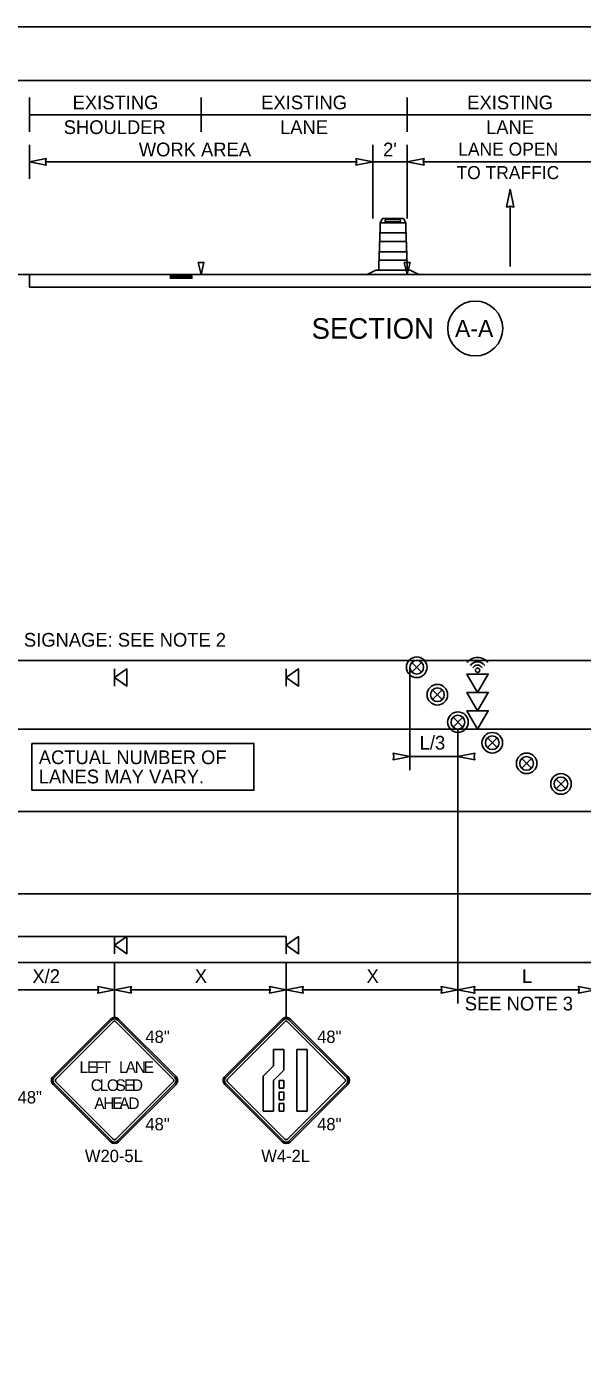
# Model space of a CAD drawing. Extents: x 99999 to 100116, y 99995 to 100013.
# Drawn here: x 100004.26 to 100007.5, y 100002.86 to 100010.69 of the extents above; entities that cross this region are included whole.
import ezdxf

# ---------------------------------------------------------------- set-up
doc = ezdxf.new("R2010")
doc.units = 0
for name, color, linetype in [('RD_ED_ShoulderPavedEdge', 7, 'Continuous'), ('RD_MK_LineEdgeWhite', 7, 'Continuous'), ('RD_MK_LineEdgeYellow', 7, 'Continuous'), ('RD_MK_LineLane', 7, 'Continuous'), ('SH_GI_PlotLimits', 7, 'Continuous'), ('SH_GI_SheetBorder', 7, 'Continuous'), ('SH_TI_Tables', 7, 'Continuous'), ('SH_TI_WZSectionCut', 7, 'Continuous'), ('TR_SN_ConstructionSigns', 7, 'Continuous'), ('TR_WZ_ArrowLeftStrRightTurn', 7, 'Continuous'), ('TR_WZ_PortableSignMountBlk-Org', 7, 'Continuous'), ('TR_WZ_SequentialArrowSign', 7, 'Continuous'), ('TR_WZ_TrafficSafetyDrum', 7, 'Continuous'), ('TR_WZ_TrafficSafetyDrumElev', 7, 'Continuous'), ('TR_WZ_WorkZoneDetails', 7, 'Continuous'), ('TR_WZ_WorkZoneTextCurrent', 7, 'Continuous')]:
    doc.layers.add(name, color=color, linetype=linetype)

msp = doc.modelspace()

# ---------------------------------------------------------------- linework, layer by layer
at = {"layer": 'RD_ED_ShoulderPavedEdge'}
for p, q in [((100000.8283, 100006.9957), (100015.62, 100006.9957)), ((100000.8283, 100005.2357), (100015.62, 100005.2357))]:
    msp.add_line(p, q, dxfattribs=at)
at = {"layer": 'RD_MK_LineEdgeWhite'}
msp.add_line((100000.8283, 100005.6357), (100015.62, 100005.6357), dxfattribs=at)
at = {"layer": 'RD_MK_LineEdgeYellow'}
msp.add_line((100000.8283, 100006.5957), (100015.62, 100006.5957), dxfattribs=at)
at = {"layer": 'RD_MK_LineLane'}
msp.add_lwpolyline([(100015.62, 100006.1157), (100000.8283, 100006.1157)], dxfattribs=at)
at = {"layer": 'SH_GI_PlotLimits'}
msp.add_lwpolyline([(99999.0625, 99999.6875), (100016.0625, 99999.6875), (100016.0625, 100010.6875), (99999.0625, 100010.6875)], close=True, dxfattribs=at)
at = {"layer": 'SH_GI_SheetBorder'}
msp.add_line((100000, 100010.375), (100015.75, 100010.375), dxfattribs=at)
at = {"layer": 'SH_TI_Tables'}
msp.add_lwpolyline([(100004.2941, 100006.511), (100005.5872, 100006.511), (100005.5872, 100006.239), (100004.2941, 100006.239)], close=True, dxfattribs=at)
at = {"layer": 'SH_TI_WZSectionCut'}
for p, q in [((100004.2794, 100010.075), (100004.2794, 100010.275)), ((100005.2794, 100010.075), (100005.2794, 100010.275)), ((100006.4794, 100010.075), (100006.4794, 100010.275)), ((100004.2794, 100010.175), (100005.2794, 100010.175)), ((100005.2794, 100010.175), (100006.4794, 100010.175)), ((100006.4794, 100010.175), (100007.6794, 100010.175)), ((100004.2794, 100009.801), (100004.2794, 100010.001)), ((100006.2794, 100009.57), (100006.2794, 100010.001)), ((100006.4794, 100009.57), (100006.4794, 100010.001)), ((100006.1857, 100009.901), (100004.3731, 100009.901)), ((100006.4794, 100009.901), (100006.2794, 100009.901)), ((100007.5857, 100009.901), (100006.5731, 100009.901)), ((100004.2794, 100009.2449), (100004.2794, 100009.1699)), ((100008.6794, 100009.2449), (100004.2794, 100009.2449)), ((100005.0964, 100009.2397), (100005.2294, 100009.2397)), ((100005.0964, 100009.2341), (100005.2294, 100009.2341)), ((100005.0964, 100009.2284), (100005.2294, 100009.2284)), ((100008.6794, 100009.1699), (100004.2794, 100009.1699)), ((100005.0964, 100009.2232), (100005.2294, 100009.2232))]:
    msp.add_line(p, q, dxfattribs=at)
for points in [[(100004.2794, 100009.901), (100004.3777, 100009.8817), (100004.3731, 100009.901), (100004.3777, 100009.9203)], [(100006.2794, 100009.901), (100006.1811, 100009.8817), (100006.1857, 100009.901), (100006.1811, 100009.9203)], [(100006.4794, 100009.901), (100006.5777, 100009.8817), (100006.5731, 100009.901), (100006.5777, 100009.9203)], [(100005.2627, 100009.3147), (100005.296, 100009.3147), (100005.2794, 100009.2449)], [(100006.4627, 100009.3147), (100006.4961, 100009.3147), (100006.4794, 100009.2449)]]:
    msp.add_lwpolyline(points, close=True, dxfattribs=at)
msp.add_circle((100006.8759, 100008.93), 0.16, dxfattribs=at)
msp.add_open_spline([(100004.2794, 100009.2449), (100004.0282, 100009.2449), (100003.9027, 100009.1828), (100003.7773, 100009.1828)], degree=2, dxfattribs=at)
at = {"layer": 'TR_SN_ConstructionSigns'}
for p, q in [((100004.7514, 100004.9058), (100004.4173, 100004.5717)), ((100004.7574, 100004.8999), (100004.4233, 100004.5658)), ((100004.4332, 100004.5558), (100004.7673, 100004.8899)), ((100004.7832, 100004.8899), (100005.1173, 100004.5558)), ((100005.1273, 100004.5658), (100004.7932, 100004.8999)), ((100005.1333, 100004.5717), (100004.7991, 100004.9058)), ((100005.7514, 100004.9058), (100005.4173, 100004.5717)), ((100005.7574, 100004.8999), (100005.4233, 100004.5658)), ((100005.4332, 100004.5558), (100005.7673, 100004.8899)), ((100005.7832, 100004.8899), (100006.1173, 100004.5558)), ((100006.1273, 100004.5658), (100005.7932, 100004.8999)), ((100006.1333, 100004.5717), (100005.7991, 100004.9058)), ((100005.7612, 100004.7279), (100005.7007, 100004.7279)), ((100005.7007, 100004.7279), (100005.7007, 100004.6334)), ((100005.7007, 100004.6334), (100005.7007, 100004.7279)), ((100005.7007, 100004.7279), (100005.7612, 100004.7279)), ((100005.7612, 100004.6083), (100005.7612, 100004.7279)), ((100005.7612, 100004.7279), (100005.7612, 100004.6083)), ((100005.8969, 100004.7279), (100005.8365, 100004.7279)), ((100005.8365, 100004.7279), (100005.8365, 100004.3679)), ((100005.8365, 100004.3679), (100005.8365, 100004.7279)), ((100005.8365, 100004.7279), (100005.8969, 100004.7279)), ((100005.8969, 100004.3679), (100005.8969, 100004.7279)), ((100005.8969, 100004.7279), (100005.8969, 100004.3679)), ((100005.7007, 100004.6334), (100005.6403, 100004.5729)), ((100005.6403, 100004.5729), (100005.7007, 100004.6334)), ((100004.7673, 100004.2058), (100004.4332, 100004.5399)), ((100005.1173, 100004.5399), (100004.7832, 100004.2058)), ((100005.7673, 100004.2058), (100005.4332, 100004.5399)), ((100005.6403, 100004.5729), (100005.6403, 100004.3679)), ((100005.6403, 100004.3679), (100005.6403, 100004.5729)), ((100005.7007, 100004.5479), (100005.7612, 100004.6083)), ((100005.7612, 100004.6083), (100005.7007, 100004.5479)), ((100005.7007, 100004.3679), (100005.7007, 100004.5479)), ((100005.7007, 100004.5479), (100005.7007, 100004.3679)), ((100005.7612, 100004.5479), (100005.7345, 100004.5479)), ((100005.7345, 100004.5479), (100005.7345, 100004.5029)), ((100005.7345, 100004.5029), (100005.7345, 100004.5479)), ((100005.7345, 100004.5479), (100005.7612, 100004.5479)), ((100005.7612, 100004.5029), (100005.7612, 100004.5479)), ((100005.7612, 100004.5479), (100005.7612, 100004.5029)), ((100006.1173, 100004.5399), (100005.7832, 100004.2058)), ((100004.4173, 100004.524), (100004.7514, 100004.1899)), ((100004.4233, 100004.53), (100004.7574, 100004.1959)), ((100004.7932, 100004.1959), (100005.1273, 100004.53)), ((100004.7991, 100004.1899), (100005.1333, 100004.524)), ((100005.4173, 100004.524), (100005.7514, 100004.1899)), ((100005.4233, 100004.53), (100005.7574, 100004.1959)), ((100005.7345, 100004.5029), (100005.7612, 100004.5029)), ((100005.7612, 100004.5029), (100005.7345, 100004.5029)), ((100005.7612, 100004.4804), (100005.7345, 100004.4804)), ((100005.7345, 100004.4804), (100005.7345, 100004.4354)), ((100005.7345, 100004.4354), (100005.7345, 100004.4804)), ((100005.7345, 100004.4804), (100005.7612, 100004.4804)), ((100005.7612, 100004.4354), (100005.7612, 100004.4804)), ((100005.7612, 100004.4804), (100005.7612, 100004.4354)), ((100005.7932, 100004.1959), (100006.1273, 100004.53)), ((100005.7991, 100004.1899), (100006.1333, 100004.524)), ((100005.7345, 100004.4354), (100005.7612, 100004.4354)), ((100005.7612, 100004.4354), (100005.7345, 100004.4354)), ((100005.7612, 100004.4129), (100005.7345, 100004.4129)), ((100005.7345, 100004.4129), (100005.7345, 100004.3679)), ((100005.7345, 100004.3679), (100005.7345, 100004.4129)), ((100005.7345, 100004.4129), (100005.7612, 100004.4129)), ((100005.7612, 100004.3679), (100005.7612, 100004.4129)), ((100005.7612, 100004.4129), (100005.7612, 100004.3679)), ((100005.6403, 100004.3679), (100005.7007, 100004.3679)), ((100005.7007, 100004.3679), (100005.6403, 100004.3679)), ((100005.7345, 100004.3679), (100005.7612, 100004.3679)), ((100005.7612, 100004.3679), (100005.7345, 100004.3679)), ((100005.8365, 100004.3679), (100005.8969, 100004.3679)), ((100005.8969, 100004.3679), (100005.8365, 100004.3679))]:
    msp.add_line(p, q, dxfattribs=at)
for centre, radius, start, end in [((100004.7753, 100004.882), 0.0338, 45, 135), ((100004.7753, 100004.882), 0.0253, 45, 135), ((100004.7753, 100004.882), 0.0113, 45, 135), ((100005.7753, 100004.882), 0.0338, 45, 135), ((100005.7753, 100004.882), 0.0253, 45, 135), ((100005.7753, 100004.882), 0.0113, 45, 135), ((100004.4412, 100004.5479), 0.0338, 135, 225.00001), ((100004.4412, 100004.5479), 0.0253, 135, 225.00001), ((100004.4412, 100004.5479), 0.0113, 135, 225.00001), ((100005.1094, 100004.5479), 0.0113, 315.00002, 45), ((100005.1094, 100004.5479), 0.0253, 315.00002, 45), ((100005.1094, 100004.5479), 0.0338, 315.00001, 45.00001), ((100005.4412, 100004.5479), 0.0338, 135, 225.00001), ((100005.4412, 100004.5479), 0.0253, 135, 225.00001), ((100005.4412, 100004.5479), 0.0113, 135, 225.00001), ((100006.1094, 100004.5479), 0.0113, 315.00002, 45), ((100006.1094, 100004.5479), 0.0253, 315.00002, 45), ((100006.1094, 100004.5479), 0.0338, 315.00001, 45.00001), ((100004.7753, 100004.2138), 0.0338, 225.00001, 315.00001), ((100004.7753, 100004.2138), 0.0253, 225.00001, 315.00002), ((100004.7753, 100004.2138), 0.0113, 225.00001, 315.00002), ((100005.7753, 100004.2138), 0.0338, 225.00001, 315.00001), ((100005.7753, 100004.2138), 0.0253, 225.00001, 315.00002), ((100005.7753, 100004.2138), 0.0113, 225.00001, 315.00002)]:
    msp.add_arc(centre, radius, start, end, dxfattribs=at)
at = {"layer": 'TR_WZ_ArrowLeftStrRightTurn'}
msp.add_line((100007.0794, 100009.6418), (100007.0794, 100009.292), dxfattribs=at)
msp.add_lwpolyline([(100007.0794, 100009.742), (100007.1, 100009.6369), (100007.0794, 100009.6418), (100007.0588, 100009.6369)], close=True, dxfattribs=at)
at = {"layer": 'TR_WZ_PortableSignMountBlk-Org'}
for p, q in [((100004.7753, 100006.8458), (100004.7753, 100006.9458)), ((100005.7753, 100006.8458), (100005.7753, 100006.9458)), ((100004.7753, 100005.2858), (100004.7753, 100005.3858)), ((100005.7753, 100005.2858), (100005.7753, 100005.3858))]:
    msp.add_line(p, q, dxfattribs=at)
for points in [[(100004.7753, 100006.8957), (100004.8471, 100006.9458), (100004.8471, 100006.8458)], [(100005.7753, 100006.8957), (100005.8471, 100006.9458), (100005.8471, 100006.8458)], [(100004.7753, 100005.3357), (100004.8471, 100005.3858), (100004.8471, 100005.2858)], [(100005.7753, 100005.3357), (100005.8471, 100005.3858), (100005.8471, 100005.2858)]]:
    msp.add_lwpolyline(points, close=True, dxfattribs=at)
at = {"layer": 'TR_WZ_SequentialArrowSign'}
for points in [[(100006.8895, 100006.8091), (100006.8278, 100006.9157), (100006.9513, 100006.9157), (100006.8895, 100006.8091)], [(100006.9513, 100006.9157), (100006.8278, 100006.9157), (100006.8895, 100006.8091), (100006.9513, 100006.9157)], [(100006.8895, 100006.7024), (100006.8278, 100006.8091), (100006.8895, 100006.8091), (100006.9513, 100006.8091), (100006.8895, 100006.7024)], [(100006.9513, 100006.8091), (100006.8895, 100006.8091), (100006.8278, 100006.8091), (100006.8895, 100006.7024), (100006.9513, 100006.8091)], [(100006.8895, 100006.5957), (100006.8278, 100006.7024), (100006.8895, 100006.7024), (100006.9513, 100006.7024), (100006.8895, 100006.5957)], [(100006.9513, 100006.7024), (100006.8895, 100006.7024), (100006.8278, 100006.7024), (100006.8895, 100006.5957), (100006.9513, 100006.7024)]]:
    msp.add_lwpolyline(points, dxfattribs=at)
msp.add_circle((100006.8895, 100006.9382), 0.0125, dxfattribs=at)
for radius, start, end in [(0.075, 37.32912, 142.67088), (0.05, 33.97816, 146.02184), (0.03, 27.15796, 152.84204)]:
    msp.add_arc((100006.8895, 100006.9382), radius, start, end, dxfattribs=at)
at = {"layer": 'TR_WZ_TrafficSafetyDrum'}
for p, q in [((100006.507, 100006.9274), (100006.5636, 100006.984)), ((100006.5636, 100006.9274), (100006.507, 100006.984)), ((100006.627, 100006.7674), (100006.6836, 100006.824)), ((100006.6836, 100006.7674), (100006.627, 100006.824)), ((100006.747, 100006.6074), (100006.8036, 100006.664)), ((100006.8036, 100006.6074), (100006.747, 100006.664)), ((100006.947, 100006.4874), (100007.0036, 100006.544)), ((100007.0036, 100006.4874), (100006.947, 100006.544)), ((100007.147, 100006.3674), (100007.2036, 100006.424)), ((100007.2036, 100006.3674), (100007.147, 100006.424)), ((100007.347, 100006.2474), (100007.4036, 100006.304)), ((100007.4036, 100006.2474), (100007.347, 100006.304))]:
    msp.add_line(p, q, dxfattribs=at)
for centre, radius in [((100006.5353, 100006.9557), 0.06), ((100006.5353, 100006.9557), 0.06), ((100006.5353, 100006.9557), 0.04), ((100006.6553, 100006.7957), 0.06), ((100006.6553, 100006.7957), 0.06), ((100006.6553, 100006.7957), 0.04), ((100006.7753, 100006.6357), 0.06), ((100006.7753, 100006.6357), 0.06), ((100006.7753, 100006.6357), 0.04), ((100006.9753, 100006.5157), 0.06), ((100006.9753, 100006.5157), 0.06), ((100006.9753, 100006.5157), 0.04), ((100007.1753, 100006.3957), 0.06), ((100007.1753, 100006.3957), 0.06), ((100007.1753, 100006.3957), 0.04), ((100007.3753, 100006.2757), 0.06), ((100007.3753, 100006.2757), 0.06), ((100007.3753, 100006.2757), 0.04)]:
    msp.add_circle(centre, radius, dxfattribs=at)
at = {"layer": 'TR_WZ_TrafficSafetyDrumElev'}
for p, q in [((100006.471, 100009.545), (100006.323, 100009.545)), ((100006.471, 100009.545), (100006.323, 100009.545)), ((100006.4365, 100009.564), (100006.3547, 100009.564)), ((100006.3547, 100009.551), (100006.4365, 100009.551)), ((100006.4738, 100009.4871), (100006.3201, 100009.4871)), ((100006.3201, 100009.4871), (100006.3201, 100009.4372)), ((100006.4738, 100009.4372), (100006.4738, 100009.4871)), ((100006.3201, 100009.4372), (100006.4738, 100009.4372)), ((100006.4775, 100009.377), (100006.3165, 100009.377)), ((100006.3165, 100009.377), (100006.3165, 100009.3271)), ((100006.3165, 100009.3271), (100006.4775, 100009.3271)), ((100006.4775, 100009.3271), (100006.4775, 100009.377))]:
    msp.add_line(p, q, dxfattribs=at)
for points in [[(100006.322, 100009.543), (100006.322, 100009.4915)], [(100006.322, 100009.543), (100006.322, 100009.4915)], [(100006.472, 100009.4915), (100006.472, 100009.543)], [(100006.472, 100009.4915), (100006.472, 100009.543)], [(100006.3201, 100009.4878), (100006.3201, 100009.4365)], [(100006.3201, 100009.4878), (100006.3201, 100009.4365)], [(100006.4738, 100009.4365), (100006.4738, 100009.4878)], [(100006.4738, 100009.4365), (100006.4738, 100009.4878)], [(100006.3183, 100009.4327), (100006.3183, 100009.3814)], [(100006.3183, 100009.4327), (100006.3183, 100009.3814)], [(100006.4757, 100009.3814), (100006.4757, 100009.4327)], [(100006.4757, 100009.3814), (100006.4757, 100009.4327)], [(100006.3146, 100009.3226), (100006.3146, 100009.27), (100006.4794, 100009.27), (100006.4794, 100009.3226)], [(100006.3146, 100009.3226), (100006.3146, 100009.27), (100006.4794, 100009.27), (100006.4794, 100009.3226)], [(100006.3165, 100009.3777), (100006.3165, 100009.3264)], [(100006.3165, 100009.3777), (100006.3165, 100009.3264)], [(100006.4775, 100009.3264), (100006.4775, 100009.3777)], [(100006.4775, 100009.3264), (100006.4775, 100009.3777)]]:
    msp.add_lwpolyline(points, dxfattribs=at)
for points in [[(100006.323, 100009.545), (100006.3361, 100009.57), (100006.4579, 100009.57), (100006.471, 100009.545)], [(100006.547, 100009.245), (100006.4968, 100009.27), (100006.2972, 100009.27), (100006.247, 100009.245)]]:
    msp.add_lwpolyline(points, close=True, dxfattribs=at)
for centre, major_axis, ratio, start_param, end_param in [((100006.3232, 100009.5426), (0, 0.00249), 0.493438, 0.177149, 1.393647), ((100006.3232, 100009.5426), (0, 0.00249), 0.493438, 0.177149, 1.393647), ((100006.3547, 100009.5575), (0, 0.0065), 0.570305, 6.283185, 9.424778), ((100006.4365, 100009.5575), (0, 0.0065), 0.570305, 3.141593, 6.283185), ((100006.4708, 100009.5426), (0, 0.00249), 0.493438, 4.889538, 6.106036), ((100006.4708, 100009.5426), (0, 0.00249), 0.493438, 4.889538, 6.106036), ((100006.3236, 100009.4846), (0, 0.00758), 0.493438, 0.4288, 1.141997), ((100006.3236, 100009.4846), (0, 0.00758), 0.493438, 0.4288, 1.141997), ((100006.4704, 100009.4846), (0, 0.00758), 0.493438, 5.141189, 5.854386), ((100006.4704, 100009.4846), (0, 0.00758), 0.493438, 5.141189, 5.854386), ((100006.3217, 100009.4296), (0, 0.00758), 0.493438, 0.4288, 1.141997), ((100006.3217, 100009.4296), (0, 0.00758), 0.493438, 0.4288, 1.141997), ((100006.4723, 100009.4296), (0, 0.00758), 0.493438, 5.141189, 5.854386), ((100006.4723, 100009.4296), (0, 0.00758), 0.493438, 5.141189, 5.854386), ((100006.318, 100009.3195), (0, 0.00758), 0.493438, 0.4288, 1.141997), ((100006.318, 100009.3195), (0, 0.00758), 0.493438, 0.4288, 1.141997), ((100006.3199, 100009.3745), (0, 0.00758), 0.493438, 0.4288, 1.141997), ((100006.3199, 100009.3745), (0, 0.00758), 0.493438, 0.4288, 1.141997), ((100006.4741, 100009.3745), (0, 0.00758), 0.493438, 5.141189, 5.854386), ((100006.4741, 100009.3745), (0, 0.00758), 0.493438, 5.141189, 5.854386), ((100006.476, 100009.3195), (0, 0.00758), 0.493438, 5.141189, 5.854386), ((100006.476, 100009.3195), (0, 0.00758), 0.493438, 5.141189, 5.854386)]:
    msp.add_ellipse(centre, major_axis=major_axis, ratio=ratio, start_param=start_param, end_param=end_param, dxfattribs=at)
at = {"layer": 'TR_WZ_WorkZoneDetails'}
for p, q in [((100006.4953, 100006.3557), (100006.4953, 100006.9557)), ((100006.7753, 100006.5957), (100006.7753, 100004.9957)), ((100006.7753, 100006.4357), (100006.4953, 100006.4357)), ((100003.1753, 100005.3858), (100005.7753, 100005.3858)), ((100004.7753, 100005.236), (100004.7753, 100004.9157)), ((100005.7753, 100005.236), (100005.7753, 100004.9157)), ((100004.6815, 100005.0757), (100004.069, 100005.0757)), ((100005.6815, 100005.0757), (100004.869, 100005.0757)), ((100006.6815, 100005.0757), (100005.869, 100005.0757)), ((100007.4815, 100005.0757), (100006.869, 100005.0757))]:
    msp.add_line(p, q, dxfattribs=at)
for points in [[(100006.4953, 100006.4357), (100006.397, 100006.455), (100006.4016, 100006.4357), (100006.397, 100006.4165)], [(100006.7753, 100006.4357), (100006.8736, 100006.455), (100006.869, 100006.4357), (100006.8736, 100006.4165)], [(100004.7753, 100005.0757), (100004.677, 100005.095), (100004.6815, 100005.0757), (100004.677, 100005.0565)], [(100004.7753, 100005.0757), (100004.8736, 100005.095), (100004.869, 100005.0757), (100004.8736, 100005.0565)], [(100005.7753, 100005.0757), (100005.677, 100005.095), (100005.6815, 100005.0757), (100005.677, 100005.0565)], [(100005.7753, 100005.0757), (100005.8736, 100005.095), (100005.869, 100005.0757), (100005.8736, 100005.0565)], [(100006.7753, 100005.0757), (100006.677, 100005.095), (100006.6815, 100005.0757), (100006.677, 100005.0565)], [(100006.7753, 100005.0757), (100006.8736, 100005.095), (100006.869, 100005.0757), (100006.8736, 100005.0565)], [(100007.5753, 100005.0757), (100007.477, 100005.095), (100007.4815, 100005.0757), (100007.477, 100005.0565)]]:
    msp.add_lwpolyline(points, close=True, dxfattribs=at)

# ---------------------------------------------------------------- texts
at = {"layer": 'SH_TI_Tables'}
for s, p in [('ACTUAL NUMBER OF', (100004.3341, 100006.391)), ('LANES MAY VARY.', (100004.3341, 100006.279))]:
    msp.add_text(s, height=0.08, rotation=360, dxfattribs=at).set_placement(p)
at = {"layer": 'SH_TI_WZSectionCut'}
for s, height, p in [('EXISTING', 0.08, (100004.5311, 100010.207)), ('EXISTING', 0.08, (100005.6296, 100010.207)), ('EXISTING', 0.08, (100006.8296, 100010.207)), ('SHOULDER', 0.08, (100004.4792, 100010.063)), ('LANE', 0.08, (100005.739, 100010.063)), ('LANE', 0.08, (100006.939, 100010.063)), ('SECTION', 0.12, (100005.9228, 100008.87)), ('A-A', 0.1, (100006.7581, 100008.88))]:
    msp.add_text(s, height=height, rotation=360, dxfattribs=at).set_placement(p)
for s, height, p in [('WORK AREA', 0.08, (100004.9165, 100009.933)), ("2'", 0.08, (100006.3394, 100009.933)), ('LANE OPEN', 0.076, (100006.7768, 100009.937)), ('TO TRAFFIC', 0.076, (100006.7667, 100009.8002))]:
    msp.add_text(s, height=height, dxfattribs=at).set_placement(p)
at = {"layer": 'TR_SN_ConstructionSigns'}
for s, p in [('48"', (100004.9551, 100004.7664)), ('48"', (100005.9551, 100004.7664)), ('48"', (100004.211, 100004.414)), ('48"', (100004.9551, 100004.2573)), ('48"', (100005.9551, 100004.2573)), ('W20-5L', (100004.6027, 100004.072)), ('W4-2L', (100005.6299, 100004.072))]:
    msp.add_text(s, height=0.072, rotation=360, dxfattribs=at).set_placement(p)
for s, p in [('L', (100004.5711, 100004.5922)), ('E', (100004.615, 100004.5922)), ('F', (100004.6609, 100004.5922)), ('T', (100004.6993, 100004.5922)), ('L', (100004.8013, 100004.5922)), ('A', (100004.8397, 100004.5922)), ('N', (100004.8924, 100004.5922)), ('E', (100004.945, 100004.5922)), ('C', (100004.6369, 100004.4867)), ('L', (100004.6882, 100004.4867)), ('O', (100004.7307, 100004.4867)), ('S', (100004.7807, 100004.4867)), ('E', (100004.83, 100004.4867)), ('D', (100004.8759, 100004.4867)), ('A', (100004.6572, 100004.3812)), ('H', (100004.7098, 100004.3812)), ('E', (100004.7625, 100004.3812)), ('A', (100004.803, 100004.3812)), ('D', (100004.8556, 100004.3812))]:
    msp.add_text(s, height=0.0675, dxfattribs=at).set_placement(p)
at = {"layer": 'TR_WZ_WorkZoneTextCurrent'}
for s, p in [('LEFT SHOULDER SIGNAGE: SEE NOTE 2', (100003.3319, 100007.0757)), ('L/3', (100006.5521, 100006.4757))]:
    msp.add_text(s, height=0.08, dxfattribs=at).set_placement(p)
for s, p in [('X/2', (100004.2968, 100005.1157)), ('X', (100005.2428, 100005.1157)), ('X', (100006.2428, 100005.1157)), ('L', (100007.1481, 100005.1157)), ('SEE NOTE 3', (100006.8151, 100004.9557))]:
    msp.add_text(s, height=0.08, rotation=360, dxfattribs=at).set_placement(p)

doc.saveas('drawing.dxf')
